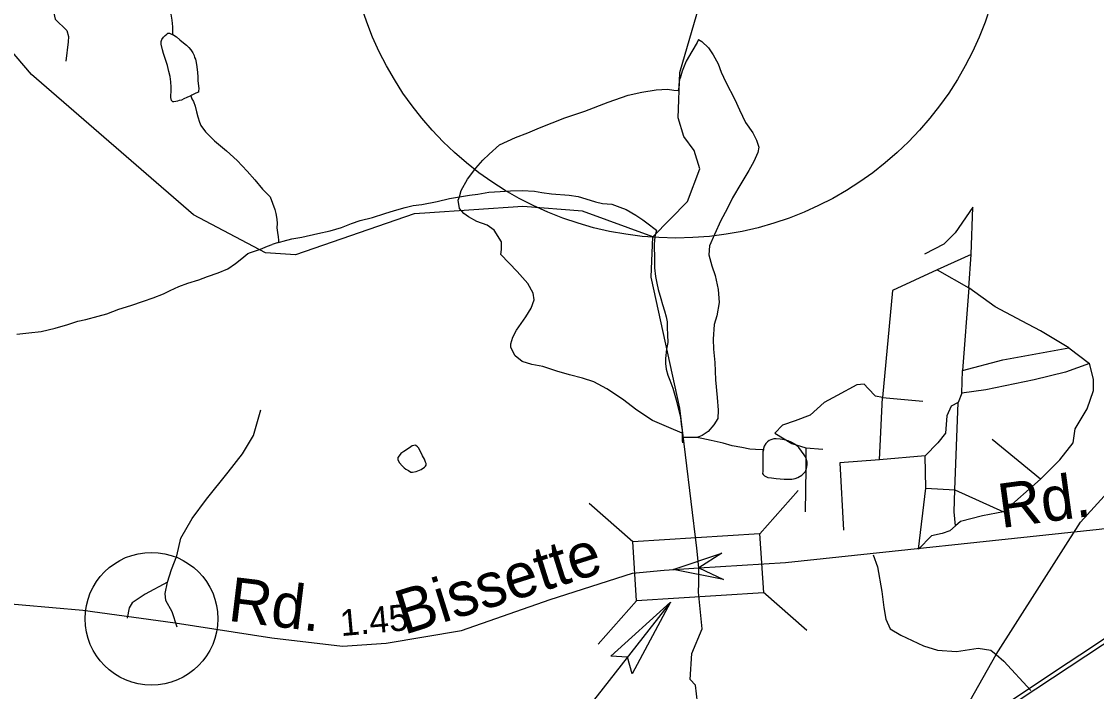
# Model space of a CAD drawing. Extents: x 2169602 to 2449496, y 721995 to 810662.
# Drawn here: x 2170168.4 to 2170289.8, y 724732 to 724807.8 of the extents above; entities that cross this region are included whole.
import ezdxf

# ---------------------------------------------------------------- set-up
doc = ezdxf.new("R2010")
doc.units = 0
for name, color, linetype in [('Old_Level_1', 7, 'Continuous'), ('Prop Dimension', 7, 'Continuous'), ('Prop Shade Medium', 7, 'Continuous'), ('Prop Terminator CELL', 7, 'Continuous')]:
    doc.layers.add(name, color=color, linetype=linetype)

msp = doc.modelspace()

# ---------------------------------------------------------------- linework, layer by layer
at = {"layer": 'Old_Level_1'}
for p, q in [((2170275.66, 724781.45), (2170271.82, 724779.69)), ((2170275.42, 724777.69), (2170275.66, 724781.45)), ((2170271.82, 724779.69), (2170275.42, 724777.69)), ((2170275.42, 724777.69), (2170274.7, 724768.31)), ((2170286.71, 724770.88), (2170289.03, 724769.11)), ((2170274.62, 724765.75), (2170274.7, 724768.31)), ((2170265.33, 724758.22), (2170265.65, 724765.27)), ((2170265.65, 724765.27), (2170270.21, 724764.87)), ((2170274.62, 724765.75), (2170274.22, 724764.71)), ((2170273.82, 724754.85), (2170274.22, 724764.71)), ((2170243.02, 724761.26), (2170243.02, 724760.74)), ((2170283.51, 724756.06), (2170278.06, 724760.54)), ((2170257, 724759.58), (2170258.92, 724759.42)), ((2170270.46, 724758.7), (2170265.33, 724758.22)), ((2170270.54, 724755.01), (2170270.46, 724758.7)), ((2170279.34, 724752.37), (2170283.51, 724756.06)), ((2170251.79, 724749.86), (2170256.13, 724754.77)), ((2170269.73, 724748.14), (2170270.54, 724755.01)), ((2170270.54, 724755.01), (2170273.82, 724754.85)), ((2170273.82, 724754.85), (2170279.34, 724752.37)), ((2170232.53, 724753.35), (2170237.45, 724749.01)), ((2170233.52, 724737.39), (2170237.86, 724742.31)), ((2170252.19, 724743.31), (2170257.1, 724738.97)), ((2170272.24, 724725.12), (2170278.48, 724736.23))]:
    msp.add_line(p, q, dxfattribs=at)
for points in [[(2170239.71, 724783.45), (2170243.63, 724787.43), (2170245.01, 724791.14), (2170244.4, 724793.18), (2170243.21, 724794.76), (2170242.59, 724796.88), (2170242.78, 724802.02), (2170244.7, 724808.61), (2170244.27, 724813.92), (2170241.93, 724819.72), (2170241.26, 724823.02)], [(2170213.95, 724786.11), (2170212.76, 724786.03), (2170199.33, 724781.39), (2170195.96, 724781.62), (2170187.83, 724785.92), (2170169.51, 724801.8), (2170166.92, 724804.82), (2170155.01, 724812.08), (2170149.86, 724813.59), (2170139.33, 724819.88), (2170137.98, 724820.92)], [(2170177.46, 724819.23), (2170177.88, 724819.1), (2170178.26, 724818.86), (2170178.78, 724818.48), (2170179.45, 724818.06), (2170179.93, 724817.68), (2170180.41, 724817.3), (2170180.99, 724816.84), (2170181.7, 724816.27), (2170182.28, 724815.79), (2170183.09, 724814.94), (2170183.85, 724814.24), (2170184.42, 724813.44), (2170184.81, 724812.58), (2170185, 724811.77), (2170185.09, 724811.01), (2170185.15, 724810.25), (2170185.11, 724809.58), (2170185.21, 724808.83), (2170185.36, 724807.93), (2170185.45, 724807.17), (2170185.46, 724806.65), (2170185.45, 724806.41), (2170185.41, 724806.31)], [(2170171.35, 724812.37), (2170171.95, 724809.23), (2170172.2, 724808.02), (2170173.51, 724806.76), (2170173.72, 724806.07), (2170173.65, 724805.48), (2170173.41, 724803.3)], [(2170187.54, 724799.38), (2170187.07, 724799.19), (2170186.74, 724799.05), (2170186.45, 724798.9), (2170186.21, 724798.86), (2170186.01, 724798.76), (2170185.83, 724798.72), (2170185.6, 724798.71), (2170185.5, 724798.71), (2170185.41, 724798.76), (2170185.35, 724798.86), (2170185.26, 724799.19), (2170185.25, 724799.42), (2170185.31, 724799.85), (2170185.3, 724800.37), (2170185.25, 724800.94), (2170185.2, 724801.56), (2170185.05, 724802.13), (2170184.87, 724802.79), (2170184.62, 724803.6), (2170184.42, 724804.17), (2170184.33, 724804.59), (2170184.19, 724805.21), (2170184.18, 724805.5), (2170184.23, 724805.73), (2170184.42, 724806.02), (2170184.61, 724806.21), (2170184.8, 724806.35), (2170184.93, 724806.45), (2170185.12, 724806.46), (2170185.41, 724806.31)], [(2170185.41, 724806.31), (2170185.5, 724806.31), (2170185.89, 724806.03), (2170186.27, 724805.7), (2170186.7, 724805.37), (2170187.04, 724805.09), (2170187.28, 724804.85), (2170187.51, 724804.56), (2170187.74, 724804.24), (2170187.89, 724803.95), (2170187.94, 724803.71), (2170188.04, 724803.52), (2170188.09, 724803.33), (2170188.18, 724802.9), (2170188.29, 724802.05), (2170188.33, 724801.48), (2170188.33, 724801.06), (2170188.39, 724800.49), (2170188.44, 724800.15), (2170188.39, 724799.92), (2170188.4, 724799.77), (2170188.1, 724799.67), (2170187.64, 724799.43), (2170187.54, 724799.38)], [(2170244.86, 724805.75), (2170244.71, 724805.41), (2170244.1, 724804.4), (2170243.48, 724803.31), (2170243.02, 724802.17), (2170242.8, 724801.36), (2170242.74, 724801.22), (2170242.65, 724800.64), (2170242.66, 724800.36), (2170242.56, 724799.98)], [(2170244.86, 724805.75), (2170245.23, 724805.51), (2170245.99, 724804.8), (2170246.52, 724803.99), (2170247.11, 724803), (2170247.44, 724802.05), (2170247.97, 724800.91), (2170248.99, 724798.97), (2170249.51, 724797.78), (2170250.17, 724796.36), (2170250.99, 724795.18), (2170251.43, 724794.38), (2170251.67, 724793.57), (2170251.58, 724792.95), (2170251.11, 724791.95), (2170250.54, 724790.95), (2170249.66, 724789.42), (2170248.71, 724787.85), (2170248.1, 724786.61), (2170247.39, 724785.28), (2170246.69, 724783.7), (2170246.12, 724782.42), (2170246.03, 724781.42), (2170246.38, 724780.14), (2170246.77, 724779.05), (2170247.1, 724777.48), (2170247.2, 724776.01), (2170246.93, 724774.49), (2170246.65, 724773.54), (2170246.51, 724771.87), (2170246.56, 724770.74), (2170246.72, 724769.22), (2170246.79, 724767.27), (2170246.98, 724765.28), (2170247.09, 724763.84), (2170247.04, 724762.89), (2170246.61, 724762.18), (2170245.95, 724761.42), (2170245.3, 724760.99), (2170244.92, 724760.84), (2170244.68, 724760.75)], [(2170187.54, 724799.38), (2170187.64, 724799.05), (2170187.83, 724798.72), (2170188.02, 724798.2), (2170188.16, 724797.58), (2170188.31, 724797.01), (2170188.51, 724796.4), (2170188.65, 724796.02), (2170189.18, 724795.31), (2170190.19, 724794.27), (2170191.56, 724793.14), (2170192.75, 724792.05), (2170193.9, 724790.87), (2170194.77, 724789.87), (2170195.63, 724788.84), (2170196.21, 724788.22), (2170196.48, 724787.94), (2170197.01, 724786.52), (2170197.12, 724786.09), (2170197.22, 724785.43), (2170197.27, 724784.95), (2170197.22, 724784.47), (2170197.32, 724783.91), (2170197.37, 724783.43), (2170197.43, 724783.05), (2170197.42, 724782.81)], [(2170217.87, 724787.96), (2170218.06, 724788.68), (2170218.76, 724789.97), (2170219.7, 724791.2), (2170220.51, 724792.11), (2170221.22, 724792.78), (2170222.39, 724793.83), (2170224.2, 724794.65), (2170225.58, 724795.18), (2170226.91, 724795.75), (2170229.79, 724796.87), (2170232.03, 724797.64), (2170234.68, 724798.66), (2170236.91, 724799.43), (2170238.47, 724799.77), (2170240.09, 724800.07), (2170241.37, 724800.11), (2170242.09, 724800.02), (2170242.56, 724799.98)], [(2170217.87, 724787.96), (2170219.02, 724788.16), (2170219.96, 724788.26), (2170221.19, 724788.5), (2170222.48, 724788.56), (2170223.62, 724788.62), (2170224.95, 724788.67), (2170226.33, 724788.58), (2170227.18, 724788.44), (2170228.27, 724788.31), (2170230.27, 724788.13), (2170231.27, 724787.99), (2170232.13, 724787.75), (2170233.22, 724787.39), (2170234.03, 724787.2), (2170235.08, 724787.11), (2170235.97, 724786.79), (2170236.69, 724786.54), (2170237.8, 724785.89), (2170238.6, 724785.37), (2170239.32, 724784.81), (2170239.84, 724784.43), (2170240.13, 724784.19)], [(2170197.42, 724782.81), (2170197.95, 724782.95), (2170198.94, 724783.2), (2170200.08, 724783.39), (2170201.88, 724783.83), (2170203.25, 724784.13), (2170204.54, 724784.51), (2170205.67, 724784.95), (2170206.67, 724785.29), (2170208.05, 724785.63), (2170209.42, 724786.06), (2170210.52, 724786.4), (2170211.75, 724786.74), (2170212.65, 724786.99), (2170213.6, 724787.08), (2170215.35, 724787.43), (2170216.73, 724787.77), (2170217.87, 724787.96)], [(2170243.02, 724761.26), (2170241.53, 724761.87), (2170239.68, 724762.67), (2170237.91, 724763.84), (2170236.29, 724765.07), (2170234.53, 724766.25), (2170233.05, 724767.04), (2170231.77, 724767.47), (2170230.29, 724767.84), (2170228.86, 724768.26), (2170227.29, 724768.77), (2170226.06, 724769.01), (2170224.96, 724769.33), (2170224.15, 724769.99), (2170223.67, 724770.94), (2170223.66, 724771.36), (2170223.9, 724772.08), (2170224.32, 724772.89), (2170225.35, 724774.41), (2170225.97, 724775.37), (2170226.3, 724776.33), (2170226.2, 724777.08), (2170225.58, 724778.17), (2170224.38, 724779.5), (2170222.56, 724781.43), (2170222.6, 724782), (2170222.61, 724782.86), (2170221.78, 724784.18), (2170220.98, 724784.74), (2170219.83, 724785.17), (2170218.88, 724785.69), (2170218.36, 724786.07), (2170217.88, 724786.63), (2170217.72, 724787.58), (2170217.87, 724787.96)], [(2170239.71, 724783.45), (2170231.77, 724786.34), (2170225.02, 724786.87), (2170213.95, 724786.11)], [(2170275.66, 724781.45), (2170275.86, 724786.78), (2170273.86, 724783.9), (2170272.58, 724782.61), (2170270.41, 724781.49)], [(2170257.38, 724715.25), (2170247.96, 724724.27), (2170244.75, 724730.8), (2170244.54, 724732.76), (2170243.94, 724733.39), (2170244.13, 724736.35), (2170245.3, 724739.14), (2170244.87, 724743.29), (2170244.89, 724744.3), (2170244.91, 724746.03), (2170244.7, 724748.24), (2170242.78, 724764.06), (2170239.52, 724778.86), (2170239.71, 724783.45)], [(2170240.13, 724784.19), (2170240.08, 724784.09), (2170239.94, 724783.43), (2170239.86, 724782.62), (2170239.86, 724782.01), (2170239.9, 724781.43), (2170239.91, 724780.68), (2170239.91, 724779.92), (2170240.01, 724778.97), (2170240.16, 724778.2), (2170240.31, 724777.49), (2170240.6, 724776.45), (2170240.79, 724775.78), (2170241.03, 724775.07), (2170241.23, 724774.41), (2170241.33, 724773.84), (2170241.32, 724773.18), (2170241.38, 724772.37), (2170241.39, 724771.51), (2170241.25, 724770.75), (2170241.16, 724769.7), (2170241.15, 724769.13), (2170241.21, 724768.47), (2170241.4, 724767.81), (2170241.65, 724767.24), (2170241.98, 724766.34), (2170242.33, 724765), (2170242.56, 724764.06), (2170242.82, 724763.01), (2170242.91, 724762.26), (2170243.02, 724761.55), (2170243.02, 724761.26)], [(2170167.87, 724772.43), (2170169.21, 724772.58), (2170170.63, 724772.73), (2170172.19, 724773.12), (2170173.62, 724773.51), (2170174.76, 724773.9), (2170175.65, 724774.09), (2170177.04, 724774.48), (2170178.04, 724774.72), (2170179.4, 724775.25), (2170180.74, 724775.68), (2170182.16, 724776.17), (2170183.26, 724776.56), (2170184.44, 724776.99), (2170185.2, 724777.37), (2170186.18, 724777.81), (2170187.18, 724778.19), (2170188.42, 724778.58), (2170189.42, 724778.97), (2170190.6, 724779.35), (2170191.69, 724779.83), (2170192.58, 724780.41), (2170193.29, 724780.99), (2170193.96, 724781.55), (2170194.28, 724781.66), (2170195.38, 724782.04), (2170196.18, 724782.37), (2170196.71, 724782.57)], [(2170197.42, 724782.81), (2170197.04, 724782.67), (2170196.71, 724782.57)], [(2170271.82, 724779.69), (2170266.77, 724777.37), (2170265.65, 724765.27)], [(2170286.71, 724770.88), (2170283.51, 724772.8), (2170281.42, 724773.92), (2170278.38, 724775.52), (2170275.42, 724777.69)], [(2170274.7, 724768.31), (2170279.26, 724769.52), (2170286.71, 724770.88)], [(2170289.03, 724769.11), (2170286.31, 724768.15), (2170282.79, 724767.27), (2170277.34, 724766.15), (2170274.62, 724765.75)], [(2170283.51, 724756.06), (2170285.67, 724758.22), (2170287.19, 724760.14), (2170287.43, 724761.74), (2170288.79, 724763.99), (2170289.51, 724766.07), (2170289.51, 724767.35), (2170289.03, 724769.11)], [(2170265.65, 724765.27), (2170264.85, 724765.43), (2170264.05, 724766.31), (2170263.57, 724766.79), (2170262.77, 724766.71), (2170260.53, 724765.51), (2170259.08, 724764.71), (2170257.48, 724763.27), (2170255.8, 724762.63), (2170254.36, 724762.14), (2170253.48, 724761.26), (2170255.4, 724760.06), (2170257, 724759.58)], [(2170274.22, 724764.71), (2170273.42, 724764.31), (2170272.94, 724763.19), (2170272.78, 724761.26), (2170271.9, 724760.14), (2170270.46, 724758.7)], [(2170184.88, 724744.39), (2170185.33, 724745.84), (2170185.96, 724747.37), (2170186.41, 724749.36), (2170187.68, 724751.61), (2170189.3, 724753.78), (2170191.74, 724756.85), (2170193.36, 724758.92), (2170194.62, 724761), (2170195.43, 724763.89)], [(2170244.68, 724760.75), (2170244.54, 724760.75), (2170244.2, 724760.74), (2170243.02, 724760.74)], [(2170243.02, 724760.74), (2170243.02, 724760.36), (2170243.07, 724760.17)], [(2170252.2, 724759.37), (2170252.06, 724759.36), (2170251.3, 724759.41), (2170250.67, 724759.44), (2170249.77, 724759.64), (2170248.67, 724759.81), (2170247.67, 724760.1), (2170246.29, 724760.42), (2170245.25, 724760.65), (2170244.68, 724760.75)], [(2170252.2, 724759.37), (2170252.14, 724759.12), (2170252.14, 724758.7), (2170252.15, 724758.13), (2170252.15, 724757.7), (2170252.15, 724757.18), (2170252.15, 724756.93), (2170252.1, 724756.7), (2170252.16, 724756.56), (2170252.31, 724756.42), (2170252.69, 724756.23), (2170253.11, 724756.18), (2170253.64, 724756.14), (2170254.11, 724756.09), (2170254.54, 724756.05), (2170255.06, 724756.05), (2170255.4, 724756.06), (2170255.78, 724756.11), (2170256.1, 724756.25), (2170256.53, 724756.49), (2170256.82, 724756.78), (2170256.96, 724756.92), (2170257.06, 724757.25), (2170257.15, 724757.67), (2170257.14, 724758.01), (2170257.04, 724758.44), (2170256.81, 724758.81), (2170256.52, 724759.2), (2170256.19, 724759.62), (2170255.81, 724759.95), (2170255.42, 724760.19), (2170254.99, 724760.37), (2170254.57, 724760.51), (2170254.09, 724760.57), (2170253.66, 724760.6), (2170253.37, 724760.61), (2170253.04, 724760.51), (2170252.85, 724760.42), (2170252.67, 724760.27), (2170252.47, 724760.08), (2170252.28, 724759.79), (2170252.2, 724759.5), (2170252.2, 724759.37)], [(2170212.11, 724757.04), (2170212.39, 724756.85), (2170212.58, 724756.85), (2170212.96, 724756.91), (2170213.53, 724757.15), (2170213.91, 724757.39), (2170214.04, 724757.53), (2170214.1, 724757.63), (2170214.09, 724757.82), (2170214.04, 724757.96), (2170213.9, 724758.29), (2170213.71, 724758.67), (2170213.42, 724759.24), (2170213.23, 724759.57), (2170213.13, 724759.71), (2170212.95, 724759.85), (2170212.85, 724759.9), (2170212.71, 724759.85), (2170212.52, 724759.8), (2170212.38, 724759.71), (2170212.1, 724759.52), (2170211.57, 724759.18), (2170211.24, 724758.95), (2170211.05, 724758.7), (2170210.91, 724758.51), (2170210.9, 724758.37), (2170210.91, 724758.22), (2170211.11, 724757.9), (2170211.39, 724757.56), (2170211.63, 724757.33), (2170211.82, 724757.19), (2170212.11, 724757.04)], [(2170257, 724759.58), (2170257, 724757.26), (2170256.92, 724752.37)], [(2170278.48, 724736.23), (2170288.01, 724751.2), (2170295.28, 724759.16)], [(2170265.33, 724758.22), (2170260.85, 724757.9), (2170261.25, 724750.29)], [(2170273.9, 724750.77), (2170273.74, 724752.37), (2170273.82, 724754.85)], [(2170084.77, 724601.82), (2170088.14, 724604.07), (2170095.45, 724608.82), (2170135.57, 724635.04), (2170314.77, 724753.35)], [(2170244.91, 724746.03), (2170254.71, 724746.62), (2170290.14, 724750.4), (2170301.24, 724751.79), (2170314.77, 724753.35)], [(2170279.34, 724752.37), (2170276.94, 724751.89), (2170274.46, 724751.25), (2170273.9, 724750.77)], [(2170273.9, 724750.77), (2170273.26, 724750.21), (2170272.38, 724749.89), (2170271.18, 724749.65), (2170269.73, 724748.14)], [(2170264.59, 724747.49), (2170265.08, 724746.14), (2170265.57, 724743.36), (2170265.81, 724741.54), (2170266.05, 724740.21), (2170266.54, 724739.12), (2170267.74, 724738.4), (2170270.28, 724737.19), (2170271.86, 724736.7), (2170274.03, 724736.58), (2170276.45, 724736.95), (2170277.9, 724736.7), (2170278.48, 724736.23)], [(2170084.77, 724601.82), (2170088.14, 724604.07), (2170095.45, 724608.82), (2170135.57, 724635.04), (2170178.74, 724663.66), (2170184.11, 724667.35), (2170185.44, 724668.22), (2170187.96, 724669.91), (2170197.6, 724676.32), (2170205.94, 724681.87), (2170213.37, 724686.68), (2170218.01, 724689.86), (2170219.78, 724691.13), (2170241.67, 724705.63), (2170256.79, 724715.62), (2170260.42, 724718.02), (2170270.91, 724724.85), (2170285.44, 724734.52), (2170289.14, 724736.98), (2170302.65, 724746)], [(2170135.81, 724743.53), (2170137.21, 724744.08), (2170145.96, 724743.48), (2170161.58, 724742.43), (2170175.33, 724741.24), (2170185.77, 724739.8), (2170196.67, 724738.1), (2170204.65, 724737.16), (2170209.57, 724737.51), (2170218.08, 724738.95), (2170228.12, 724742.43), (2170237.4, 724745.42), (2170240.98, 724745.77), (2170244.91, 724746.03)], [(2170184.88, 724744.39), (2170182.35, 724743.04), (2170180.91, 724742.05), (2170180.55, 724741.5), (2170180.34, 724740.33)], [(2170185.97, 724739.3), (2170185.42, 724741.05), (2170184.7, 724742.32), (2170184.61, 724743.13), (2170184.88, 724744.39)], [(2170278.48, 724736.23), (2170279.35, 724735.49), (2170282.4, 724732.17)]]:
    msp.add_lwpolyline(points, dxfattribs=at)
for points in [[(2170237.45, 724749.01), (2170251.78, 724749.89), (2170252.2, 724743.19), (2170237.86, 724742.31)], [(2170247.7, 724744.71), (2170242.02, 724745.84), (2170247.5, 724747.7), (2170244.91, 724746.03)]]:
    msp.add_lwpolyline(points, close=True, dxfattribs=at)
msp.add_circle((2170242.32, 724820.48), 37.18, dxfattribs=at)
at = {"layer": 'Prop Dimension'}
msp.add_line((2170241.72, 724742.16), (2170228.44, 724725.24), dxfattribs=at)
at = {"layer": 'Prop Shade Medium'}
msp.add_circle((2170183.08, 724740.27), 7.5, dxfattribs=at)
at = {"layer": 'Prop Terminator CELL'}
msp.add_lwpolyline([(2170234.95, 724736.04), (2170241.72, 724742.16), (2170237.39, 724734.05), (2170236.85, 724735.94)], close=True, dxfattribs=at)

# ---------------------------------------------------------------- texts
at = {"layer": 'Old_Level_1'}
for s, height, rotation, p in [('Rd.', 5, 7.7059, (2170279.06, 724750.51)), ('Bissette', 5, 17.4766, (2170211.62, 724738.43)), ('Rd.', 5, 353.085, (2170191.62, 724740.05)), ('1.45', 2.971, 5.1522, (2170204.5, 724738.3))]:
    msp.add_text(s, height=height, rotation=rotation, dxfattribs=at).set_placement(p)

doc.saveas('drawing.dxf')
